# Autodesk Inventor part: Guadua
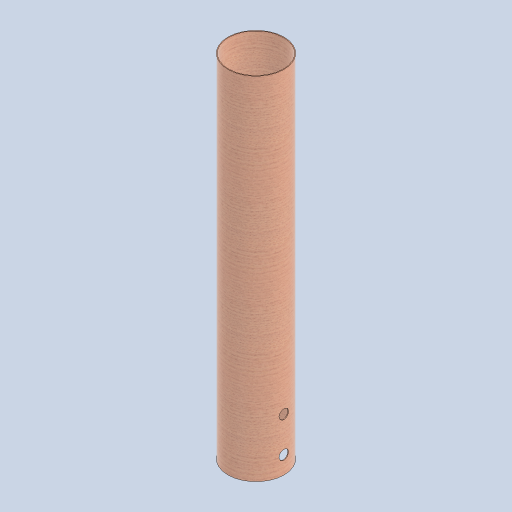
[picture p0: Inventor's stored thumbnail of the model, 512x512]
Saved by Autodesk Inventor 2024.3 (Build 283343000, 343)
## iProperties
Created: 2025-10
Part Number: Guadua
Material: Madera (roble)
Document SubType Name: Modeling
Designer: Asus
Density: 0.76 g/cm^3
Appearance: Roble blanco - Natural brillo medio
Author: Asus
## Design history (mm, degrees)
sketch "Boceto1"
  geometry: C1 r 80 at (0, 0); C2 r 78 at (0, 0); 1 further point
  constraints: 2 centre point, 2 coincident
  dimensions: "d0" = 160 diameter of C1; "d1" = 2 radial gap between concentric circles of C1 C2
extrude "Extrusión1" new body sketch "Boceto1" distance "d2" = 1000; taper "d3" = 0 deg
node "Plano de trabajo1"
sketch "Boceto2"
  geometry: L1 (-200, 0)-(1200, 0) reference; L2 (0, 112)-(0, -112) reference; 3 further points
  dimensions: "d4" = 0 distance from line of L1 point (150, 0); "d5" = 0 distance from line of L1 point (50, 0); "d6" = 50 distance from line of point (50, 0) L2; "d7" = 100 distance of point (50, 0) point (150, 0)
hole "Agujero1" sketch "Boceto2" at (50, 0), (150, 0) diameter "d8" = 27; stored, may be unused: countersink angle "d12" = 90 deg, drill point angle "d14" = 118 deg; dims "d9" = 6, "d10" = 4, "d11" = 2, "d13" = 8
node "Sólido1"
